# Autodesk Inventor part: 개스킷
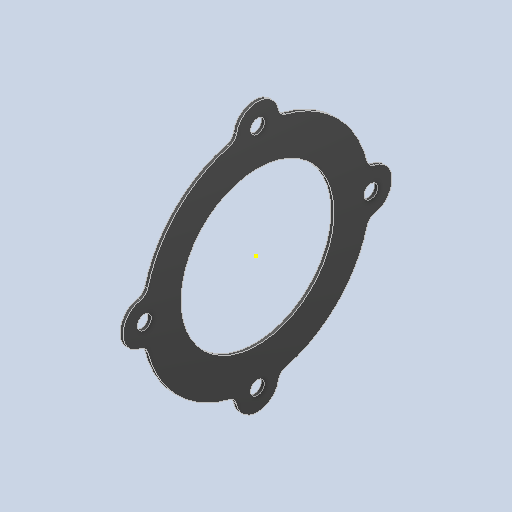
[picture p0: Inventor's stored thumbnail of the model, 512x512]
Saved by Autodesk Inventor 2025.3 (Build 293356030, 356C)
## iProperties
Created: 2025-08
Part Number: 개스킷
Material: 황동, 연질 노란색
Document SubType Name: Modeling
Designer: user
Density: 8.47 g/cm^3
Appearance: 기본값
Author: jhkim
Sending System: Autodesk Inventor 2026
Preprocessor: ST-DEVELOPER v20.1
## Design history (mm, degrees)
sketch "스케치1"
  geometry: 1 further point
  constraints: 1 other
feature "솔리드2"
node "솔리드1"
